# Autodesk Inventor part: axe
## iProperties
Author: robert
Shininess: 20.0
Angle Display Precision: 2
Document Length Units: 11269
Document Angle Units: 11283
Document Time Units: 11279
Document Mass Units: 11290
Document Length Units Precision: 3
Document Angle Units Precision: 2
Compacted: True
PropertySet Name: _Private Model Information
Created: 2002-06
Part Number: axe
Material: Par défaut
Document SubType Name: Modélisation
Designer: robert
Control State: 0
Master: False
Checked Out: False
PropertySet Name: Design Tracking Control
Density: 0.0
Volumn: 0.0
Area: 0.0
PropertySet Name: Model Information
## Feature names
1. Extrusion1
2. Chanfrein1 [Chamfer]
